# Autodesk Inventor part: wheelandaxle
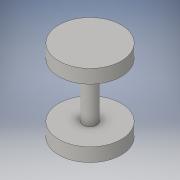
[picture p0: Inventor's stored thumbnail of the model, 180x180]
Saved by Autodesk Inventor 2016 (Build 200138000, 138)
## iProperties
Created: 2017-02
Part Number: wheelandaxle
Material: Generic
Document SubType Name: Modeling
Designer: Corey
Density: 1 g/cm^3
Appearance: Default
Author: Corey
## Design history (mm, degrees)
sketch "Sketch1"
  geometry: C1 r 14.605 at (0, 0); 1 further point
  constraints: 1 centre point, 1 coincident
  dimensions: "d0" = 29.21 diameter of C1 (= 1.15 x n)
extrude "Extrusion1" new body sketch "Sketch1" distance "d1" = 6.35 (= 0.25 x n); taper "d2" = 0 deg
sketch "Sketch2"
  geometry: C1 r 3.175 at (0, 0); 1 further point
  constraints: 1 centre point, 1 coincident
  dimensions: "d3" = 6.35 diameter of C1 (= 0.25 x n)
extrude "Extrusion2" join sketch "Sketch2" distance "d4" = 25.4 (= n); taper "d5" = 0 deg
sketch "Sketch3"
  geometry: C1 r 14.605 at (0, 0); 1 further point
  constraints: 1 centre point, 1 coincident
  dimensions: "d6" = 29.21 diameter of C1 (= 1.15 x n)
extrude "Extrusion3" join sketch "Sketch3" distance "d7" = 6.35 (= 0.25 x n); taper "d8" = 0 deg
body "Solid1"
other parameters: "n" = 25.4 [user parameter; used in 6 equation terms]
